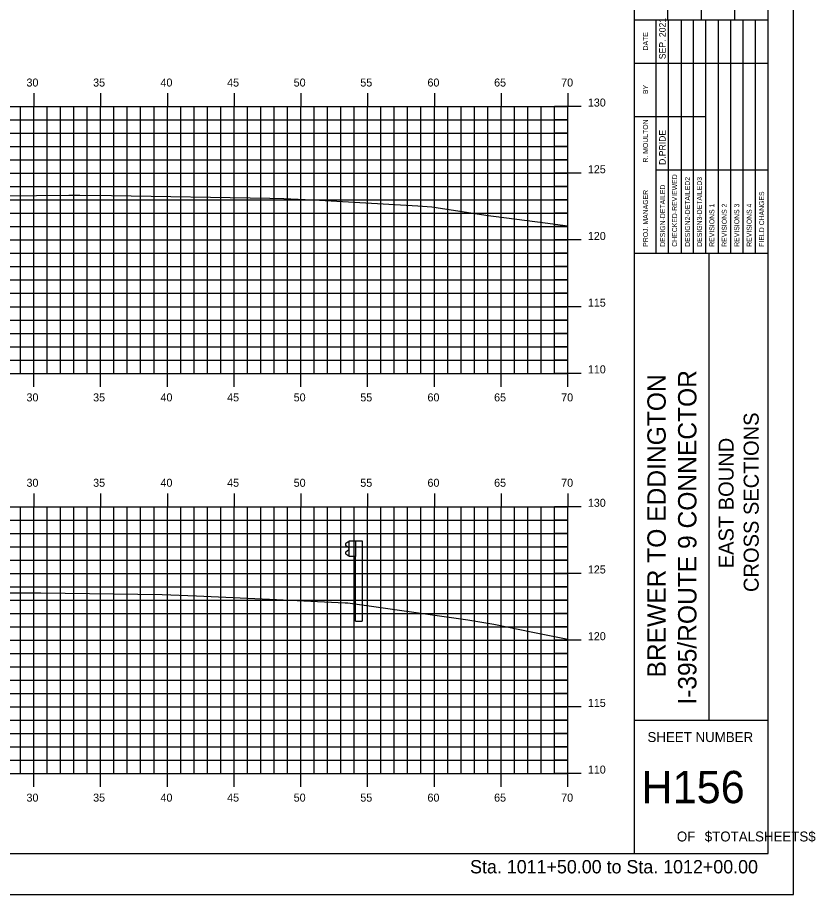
# Model space of a CAD drawing. Extents: x 852404 to 852575, y 365624 to 365734.
# Drawn here: x 852515.6 to 852575.3, y 365624 to 365689.7 of the extents above; entities that cross this region are included whole.
import ezdxf

# ---------------------------------------------------------------- set-up
doc = ezdxf.new("R2010")
doc.units = 0
for name, color, linetype in [('BORDER', 7, 'Continuous'), ('H_V ANNOTATION', 7, 'Continuous'), ('M_Guardrail', 7, 'Continuous'), ('M_Roadway_Centerline', 7, 'Continuous'), ('MAJOR', 7, 'Continuous'), ('MINOR', 7, 'Continuous'), ('PLOT BOUNDARY', 7, 'Continuous'), ('S_Roadway_Centerline', 7, 'Continuous')]:
    doc.layers.add(name, color=color, linetype=linetype)

msp = doc.modelspace()

# ---------------------------------------------------------------- linework, layer by layer
at = {"layer": 'BORDER'}
for p, q in [((852561.792, 365627.027), (852561.792, 365732.027)), ((852564.292, 365689.53), (852564.292, 365698.177)), ((852566.792, 365689.53), (852566.792, 365698.177)), ((852569.292, 365689.53), (852569.292, 365698.177)), ((852561.792, 365689.53), (852571.792, 365689.53)), ((852561.792, 365672.03), (852571.792, 365672.03)), ((852567.383, 365637.03), (852567.383, 365672.03)), ((852561.792, 365637.03), (852571.792, 365637.03))]:
    msp.add_line(p, q, dxfattribs=at)
msp.add_lwpolyline([(852411.792, 365627.027), (852571.792, 365627.027), (852571.792, 365732.027), (852411.792, 365732.027)], close=True, dxfattribs=at)
for points in [[(852563.407, 365686.28), (852563.407, 365689.53)], [(852564.339, 365672.033), (852564.339, 365689.53)], [(852565.271, 365689.53), (852565.271, 365672.033)], [(852566.203, 365672.033), (852566.203, 365689.53)], [(852567.135, 365672.033), (852567.135, 365689.53)], [(852568.066, 365672.033), (852568.066, 365689.53)], [(852568.998, 365672.033), (852568.998, 365689.53)], [(852569.93, 365672.033), (852569.93, 365689.53)], [(852570.861, 365672.033), (852570.861, 365689.53)], [(852563.408, 365672.033), (852563.408, 365688.824)], [(852561.792, 365686.28), (852571.792, 365686.28)], [(852561.792, 365682.28), (852563.408, 365682.28)], [(852563.407, 365682.28), (852567.134, 365682.28)], [(852563.407, 365678.28), (852571.792, 365678.28)]]:
    msp.add_lwpolyline(points, dxfattribs=at)
at = {"layer": 'M_Guardrail'}
for p, q in [((852540.407, 365650.464), (852540.896, 365650.464)), ((852540.407, 365649.297), (852540.407, 365650.464)), ((852540.896, 365650.464), (852541.388, 365650.464)), ((852540.896, 365650.464), (852540.896, 365649.297)), ((852541.388, 365650.464), (852541.388, 365644.464)), ((852540.308, 365650.369), (852540.165, 365650.269)), ((852540.165, 365650.126), (852540.36, 365649.99)), ((852540.36, 365649.77), (852540.165, 365649.634)), ((852540.407, 365650.391), (852540.325, 365650.376)), ((852540.394, 365649.926), (852540.394, 365649.835)), ((852540.165, 365649.491), (852540.308, 365649.391)), ((852540.325, 365649.384), (852540.407, 365649.37)), ((852540.896, 365649.297), (852540.407, 365649.297)), ((852540.896, 365644.464), (852540.896, 365649.297)), ((852540.896, 365644.464), (852541.388, 365644.464))]:
    msp.add_line(p, q, dxfattribs=at)
for centre, major_axis, start_param, end_param in [((852540.215, 365650.198), (-0.0877, 0), 5.323254, 7.243116), ((852540.332, 365650.335), (-0.0417, 0), 4.886922, 5.323254), ((852540.315, 365649.926), (0.0789, 0), 0, 0.959931), ((852540.315, 365649.835), (0.0789, 0), 5.323254, 6.283185), ((852540.215, 365649.563), (-0.0877, 0), 5.323254, 7.243116), ((852540.332, 365649.425), (-0.0417, 0), 0.959931, 1.396263)]:
    msp.add_ellipse(centre, major_axis=major_axis, ratio=0.995501, start_param=start_param, end_param=end_param, dxfattribs=at)
at = {"layer": 'MAJOR'}
for p, q in [((852516.792, 365684.029), (852516.792, 365683.027)), ((852521.792, 365684.029), (852521.792, 365683.027)), ((852526.792, 365684.029), (852526.792, 365683.027)), ((852531.792, 365684.029), (852531.792, 365683.027)), ((852536.792, 365684.029), (852536.792, 365683.027)), ((852541.792, 365684.029), (852541.792, 365683.027)), ((852546.792, 365684.029), (852546.792, 365683.027)), ((852551.792, 365684.029), (852551.792, 365683.027)), ((852556.792, 365684.029), (852556.792, 365683.027)), ((852416.792, 365683.027), (852556.792, 365683.027)), ((852416.792, 365683.027), (852556.792, 365683.027)), ((852516.792, 365663.027), (852516.792, 365683.027)), ((852521.792, 365663.027), (852521.792, 365683.027)), ((852526.792, 365663.027), (852526.792, 365683.027)), ((852531.792, 365663.027), (852531.792, 365683.027)), ((852536.792, 365663.027), (852536.792, 365683.027)), ((852541.792, 365663.027), (852541.792, 365683.027)), ((852546.792, 365663.027), (852546.792, 365683.027)), ((852551.792, 365663.027), (852551.792, 365683.027)), ((852557.794, 365683.027), (852555.79, 365683.027)), ((852556.792, 365663.027), (852556.792, 365683.027)), ((852556.792, 365663.027), (852556.792, 365683.027)), ((852416.792, 365678.027), (852556.792, 365678.027)), ((852557.794, 365678.027), (852555.79, 365678.027)), ((852416.792, 365673.027), (852556.792, 365673.027)), ((852557.794, 365673.027), (852555.79, 365673.027)), ((852416.792, 365668.027), (852556.792, 365668.027)), ((852557.794, 365668.027), (852555.79, 365668.027)), ((852416.792, 365663.027), (852556.792, 365663.027)), ((852416.792, 365663.027), (852556.792, 365663.027)), ((852516.792, 365662.025), (852516.792, 365663.027)), ((852521.792, 365662.025), (852521.792, 365663.027)), ((852526.792, 365662.025), (852526.792, 365663.027)), ((852531.792, 365662.025), (852531.792, 365663.027)), ((852536.792, 365662.025), (852536.792, 365663.027)), ((852541.792, 365662.025), (852541.792, 365663.027)), ((852546.792, 365662.025), (852546.792, 365663.027)), ((852551.792, 365662.025), (852551.792, 365663.027)), ((852557.794, 365663.027), (852555.79, 365663.027)), ((852556.792, 365662.025), (852556.792, 365663.027)), ((852516.792, 365654.029), (852516.792, 365653.027)), ((852521.792, 365654.029), (852521.792, 365653.027)), ((852526.792, 365654.029), (852526.792, 365653.027)), ((852531.792, 365654.029), (852531.792, 365653.027)), ((852536.792, 365654.029), (852536.792, 365653.027)), ((852541.792, 365654.029), (852541.792, 365653.027)), ((852546.792, 365654.029), (852546.792, 365653.027)), ((852551.792, 365654.029), (852551.792, 365653.027)), ((852556.792, 365654.029), (852556.792, 365653.027)), ((852416.792, 365653.027), (852556.792, 365653.027)), ((852416.792, 365653.027), (852556.792, 365653.027)), ((852516.792, 365633.027), (852516.792, 365653.027)), ((852521.792, 365633.027), (852521.792, 365653.027)), ((852526.792, 365633.027), (852526.792, 365653.027)), ((852531.792, 365633.027), (852531.792, 365653.027)), ((852536.792, 365633.027), (852536.792, 365653.027)), ((852541.792, 365633.027), (852541.792, 365653.027)), ((852546.792, 365633.027), (852546.792, 365653.027)), ((852551.792, 365633.027), (852551.792, 365653.027)), ((852557.794, 365653.027), (852555.79, 365653.027)), ((852556.792, 365633.027), (852556.792, 365653.027)), ((852556.792, 365633.027), (852556.792, 365653.027)), ((852416.792, 365648.027), (852556.792, 365648.027)), ((852557.794, 365648.027), (852555.79, 365648.027)), ((852416.792, 365643.027), (852556.792, 365643.027)), ((852557.794, 365643.027), (852555.79, 365643.027)), ((852416.792, 365638.027), (852556.792, 365638.027)), ((852557.794, 365638.027), (852555.79, 365638.027)), ((852416.792, 365633.027), (852556.792, 365633.027)), ((852416.792, 365633.027), (852556.792, 365633.027)), ((852516.792, 365632.025), (852516.792, 365633.027)), ((852521.792, 365632.025), (852521.792, 365633.027)), ((852526.792, 365632.025), (852526.792, 365633.027)), ((852531.792, 365632.025), (852531.792, 365633.027)), ((852536.792, 365632.025), (852536.792, 365633.027)), ((852541.792, 365632.025), (852541.792, 365633.027)), ((852546.792, 365632.025), (852546.792, 365633.027)), ((852551.792, 365632.025), (852551.792, 365633.027)), ((852557.794, 365633.027), (852555.79, 365633.027)), ((852556.792, 365632.025), (852556.792, 365633.027))]:
    msp.add_line(p, q, dxfattribs=at)
at = {"layer": 'MINOR'}
for p, q in [((852515.792, 365663.027), (852515.792, 365683.027)), ((852517.792, 365663.027), (852517.792, 365683.027)), ((852518.792, 365663.027), (852518.792, 365683.027)), ((852519.792, 365663.027), (852519.792, 365683.027)), ((852520.792, 365663.027), (852520.792, 365683.027)), ((852522.792, 365663.027), (852522.792, 365683.027)), ((852523.792, 365663.027), (852523.792, 365683.027)), ((852524.792, 365663.027), (852524.792, 365683.027)), ((852525.792, 365663.027), (852525.792, 365683.027)), ((852527.792, 365663.027), (852527.792, 365683.027)), ((852528.792, 365663.027), (852528.792, 365683.027)), ((852529.792, 365663.027), (852529.792, 365683.027)), ((852530.792, 365663.027), (852530.792, 365683.027)), ((852532.792, 365663.027), (852532.792, 365683.027)), ((852533.792, 365663.027), (852533.792, 365683.027)), ((852534.792, 365663.027), (852534.792, 365683.027)), ((852535.792, 365663.027), (852535.792, 365683.027)), ((852537.792, 365663.027), (852537.792, 365683.027)), ((852538.792, 365663.027), (852538.792, 365683.027)), ((852539.792, 365663.027), (852539.792, 365683.027)), ((852540.792, 365663.027), (852540.792, 365683.027)), ((852542.792, 365663.027), (852542.792, 365683.027)), ((852543.792, 365663.027), (852543.792, 365683.027)), ((852544.792, 365663.027), (852544.792, 365683.027)), ((852545.792, 365663.027), (852545.792, 365683.027)), ((852547.792, 365663.027), (852547.792, 365683.027)), ((852548.792, 365663.027), (852548.792, 365683.027)), ((852549.792, 365663.027), (852549.792, 365683.027)), ((852550.792, 365663.027), (852550.792, 365683.027)), ((852552.792, 365663.027), (852552.792, 365683.027)), ((852553.792, 365663.027), (852553.792, 365683.027)), ((852554.792, 365663.027), (852554.792, 365683.027)), ((852555.792, 365663.027), (852555.792, 365683.027)), ((852416.792, 365682.027), (852556.792, 365682.027)), ((852556.792, 365682.027), (852555.79, 365682.027)), ((852416.792, 365681.027), (852556.792, 365681.027)), ((852556.792, 365681.027), (852555.79, 365681.027)), ((852416.792, 365680.027), (852556.792, 365680.027)), ((852556.792, 365680.027), (852555.79, 365680.027)), ((852416.792, 365679.027), (852556.792, 365679.027)), ((852556.792, 365679.027), (852555.79, 365679.027)), ((852416.792, 365677.027), (852556.792, 365677.027)), ((852556.792, 365677.027), (852555.79, 365677.027)), ((852416.792, 365676.027), (852556.792, 365676.027)), ((852556.792, 365676.027), (852555.79, 365676.027)), ((852416.792, 365675.027), (852556.792, 365675.027)), ((852556.792, 365675.027), (852555.79, 365675.027)), ((852416.792, 365674.027), (852556.792, 365674.027)), ((852556.792, 365674.027), (852555.79, 365674.027)), ((852416.792, 365672.027), (852556.792, 365672.027)), ((852556.792, 365672.027), (852555.79, 365672.027)), ((852416.792, 365671.027), (852556.792, 365671.027)), ((852556.792, 365671.027), (852555.79, 365671.027)), ((852416.792, 365670.027), (852556.792, 365670.027)), ((852556.792, 365670.027), (852555.79, 365670.027)), ((852416.792, 365669.027), (852556.792, 365669.027)), ((852556.792, 365669.027), (852555.79, 365669.027)), ((852416.792, 365667.027), (852556.792, 365667.027)), ((852556.792, 365667.027), (852555.79, 365667.027)), ((852416.792, 365666.027), (852556.792, 365666.027)), ((852556.792, 365666.027), (852555.79, 365666.027)), ((852416.792, 365665.027), (852556.792, 365665.027)), ((852556.792, 365665.027), (852555.79, 365665.027)), ((852416.792, 365664.027), (852556.792, 365664.027)), ((852556.792, 365664.027), (852555.79, 365664.027)), ((852515.792, 365633.027), (852515.792, 365653.027)), ((852517.792, 365633.027), (852517.792, 365653.027)), ((852518.792, 365633.027), (852518.792, 365653.027)), ((852519.792, 365633.027), (852519.792, 365653.027)), ((852520.792, 365633.027), (852520.792, 365653.027)), ((852522.792, 365633.027), (852522.792, 365653.027)), ((852523.792, 365633.027), (852523.792, 365653.027)), ((852524.792, 365633.027), (852524.792, 365653.027)), ((852525.792, 365633.027), (852525.792, 365653.027)), ((852527.792, 365633.027), (852527.792, 365653.027)), ((852528.792, 365633.027), (852528.792, 365653.027)), ((852529.792, 365633.027), (852529.792, 365653.027)), ((852530.792, 365633.027), (852530.792, 365653.027)), ((852532.792, 365633.027), (852532.792, 365653.027)), ((852533.792, 365633.027), (852533.792, 365653.027)), ((852534.792, 365633.027), (852534.792, 365653.027)), ((852535.792, 365633.027), (852535.792, 365653.027)), ((852537.792, 365633.027), (852537.792, 365653.027)), ((852538.792, 365633.027), (852538.792, 365653.027)), ((852539.792, 365633.027), (852539.792, 365653.027)), ((852540.792, 365633.027), (852540.792, 365653.027)), ((852542.792, 365633.027), (852542.792, 365653.027)), ((852543.792, 365633.027), (852543.792, 365653.027)), ((852544.792, 365633.027), (852544.792, 365653.027)), ((852545.792, 365633.027), (852545.792, 365653.027)), ((852547.792, 365633.027), (852547.792, 365653.027)), ((852548.792, 365633.027), (852548.792, 365653.027)), ((852549.792, 365633.027), (852549.792, 365653.027)), ((852550.792, 365633.027), (852550.792, 365653.027)), ((852552.792, 365633.027), (852552.792, 365653.027)), ((852553.792, 365633.027), (852553.792, 365653.027)), ((852554.792, 365633.027), (852554.792, 365653.027)), ((852555.792, 365633.027), (852555.792, 365653.027)), ((852416.792, 365652.027), (852556.792, 365652.027)), ((852556.792, 365652.027), (852555.79, 365652.027)), ((852416.792, 365651.027), (852556.792, 365651.027)), ((852556.792, 365651.027), (852555.79, 365651.027)), ((852416.792, 365650.027), (852556.792, 365650.027)), ((852556.792, 365650.027), (852555.79, 365650.027)), ((852416.792, 365649.027), (852556.792, 365649.027)), ((852556.792, 365649.027), (852555.79, 365649.027)), ((852416.792, 365647.027), (852556.792, 365647.027)), ((852556.792, 365647.027), (852555.79, 365647.027)), ((852416.792, 365646.027), (852556.792, 365646.027)), ((852556.792, 365646.027), (852555.79, 365646.027)), ((852416.792, 365645.027), (852556.792, 365645.027)), ((852556.792, 365645.027), (852555.79, 365645.027)), ((852416.792, 365644.027), (852556.792, 365644.027)), ((852556.792, 365644.027), (852555.79, 365644.027)), ((852416.792, 365642.027), (852556.792, 365642.027)), ((852556.792, 365642.027), (852555.79, 365642.027)), ((852416.792, 365641.027), (852556.792, 365641.027)), ((852556.792, 365641.027), (852555.79, 365641.027)), ((852416.792, 365640.027), (852556.792, 365640.027)), ((852556.792, 365640.027), (852555.79, 365640.027)), ((852416.792, 365639.027), (852556.792, 365639.027)), ((852556.792, 365639.027), (852555.79, 365639.027)), ((852416.792, 365637.027), (852556.792, 365637.027)), ((852556.792, 365637.027), (852555.79, 365637.027)), ((852416.792, 365636.027), (852556.792, 365636.027)), ((852556.792, 365636.027), (852555.79, 365636.027)), ((852416.792, 365635.027), (852556.792, 365635.027)), ((852556.792, 365635.027), (852555.79, 365635.027)), ((852416.792, 365634.027), (852556.792, 365634.027)), ((852556.792, 365634.027), (852555.79, 365634.027))]:
    msp.add_line(p, q, dxfattribs=at)
at = {"layer": 'PLOT BOUNDARY'}
msp.add_lwpolyline([(852403.699, 365623.968), (852573.699, 365623.968), (852573.699, 365733.968), (852403.699, 365733.968)], close=True, dxfattribs=at)
at = {"layer": 'S_Roadway_Centerline'}
for points in [[(852512.087, 365676.312), (852519.423, 365676.382), (852520.245, 365676.382), (852522.605, 365676.362), (852534.472, 365676.154), (852535.51, 365676.139), (852538.19, 365676.015), (852545.547, 365675.583), (852546.61, 365675.503), (852550.653, 365674.892), (852555.096, 365674.316), (852556.792, 365674.074)], [(852514.953, 365646.571), (852516.292, 365646.575), (852517.315, 365646.569), (852526.407, 365646.462), (852528.971, 365646.362), (852534.446, 365646.095), (852540.113, 365645.836), (852540.315, 365645.823), (852549.292, 365644.561), (852551.256, 365644.218), (852554.042, 365643.664), (852556.792, 365643.116)]]:
    msp.add_lwpolyline(points, dxfattribs=at)

# ---------------------------------------------------------------- texts
at = {"layer": 'BORDER'}
for s, height, p in [('SEP. 2021', 0.4845, (852564.115, 365686.575)), ('DATE', 0.3714, (852562.796, 365687.235)), ('BY', 0.3714, (852562.796, 365683.965)), ('R. MOULTON', 0.3727, (852562.796, 365678.832)), ('D.PRIDE', 0.4845, (852564.115, 365678.653)), ('CHECKED-REVIEWED', 0.37275, (852564.973, 365672.518)), ('DESIGN2-DETAILED2', 0.37275, (852565.942, 365672.518)), ('DESIGN3-DETAILED3', 0.37275, (852566.836, 365672.518)), ('DESIGN-DETAILED', 0.37275, (852564.079, 365672.518)), ('PROJ. MANAGER', 0.37275, (852562.796, 365672.518)), ('FIELD CHANGES', 0.37275, (852571.495, 365672.518)), ('REVISIONS 1', 0.37275, (852567.768, 365672.518)), ('REVISIONS 2', 0.37275, (852568.7, 365672.518)), ('REVISIONS 3', 0.37275, (852569.631, 365672.518)), ('REVISIONS 4', 0.37275, (852570.563, 365672.518)), ('I-395/ROUTE 9 CONNECTOR', 1.37787, (852566.427, 365638.192)), ('BREWER TO EDDINGTON', 1.37787, (852564.126, 365640.231)), ('CROSS SECTIONS', 1.125, (852571.089, 365646.638)), ('EAST BOUND', 1.125, (852569.21, 365648.418))]:
    msp.add_text(s, height=height, rotation=90, dxfattribs=at).set_placement(p)
for s, height, p in [('SHEET NUMBER', 0.74527, (852562.757, 365635.393)), ('H156', 2.4194, (852562.307, 365630.809)), ('$TOTALSHEETS$', 0.74527, (852567.049, 365627.94)), ('OF', 0.7453, (852564.959, 365627.94))]:
    msp.add_text(s, height=height, dxfattribs=at).set_placement(p)
at = {"layer": 'H_V ANNOTATION'}
for s, height, p in [('30', 0.6, (852516.241, 365684.527)), ('35', 0.6, (852521.233, 365684.527)), ('40', 0.6, (852526.278, 365684.527)), ('45', 0.6, (852531.27, 365684.527)), ('50', 0.6, (852536.256, 365684.527)), ('55', 0.6, (852541.248, 365684.527)), ('60', 0.6, (852546.278, 365684.527)), ('65', 0.6, (852551.27, 365684.527)), ('70', 0.6, (852556.294, 365684.527)), ('130', 0.6, (852558.292, 365683.027)), ('125', 0.6, (852558.292, 365678.027)), ('120', 0.6, (852558.292, 365673.027)), ('115', 0.6, (852558.292, 365668.027)), ('110', 0.6, (852558.292, 365663.027)), ('30', 0.6, (852516.241, 365660.927)), ('35', 0.6, (852521.233, 365660.927)), ('40', 0.6, (852526.278, 365660.927)), ('45', 0.6, (852531.27, 365660.927)), ('50', 0.6, (852536.256, 365660.927)), ('55', 0.6, (852541.248, 365660.927)), ('60', 0.6, (852546.278, 365660.927)), ('65', 0.6, (852551.27, 365660.927)), ('70', 0.6, (852556.294, 365660.927)), ('30', 0.6, (852516.241, 365654.527)), ('35', 0.6, (852521.233, 365654.527)), ('40', 0.6, (852526.278, 365654.527)), ('45', 0.6, (852531.27, 365654.527)), ('50', 0.6, (852536.256, 365654.527)), ('55', 0.6, (852541.248, 365654.527)), ('60', 0.6, (852546.278, 365654.527)), ('65', 0.6, (852551.27, 365654.527)), ('70', 0.6, (852556.294, 365654.527)), ('130', 0.6, (852558.292, 365653.027)), ('125', 0.6, (852558.292, 365648.027)), ('120', 0.6, (852558.292, 365643.027)), ('115', 0.6, (852558.292, 365638.027)), ('110', 0.6, (852558.292, 365633.027)), ('30', 0.6, (852516.241, 365630.927)), ('35', 0.6, (852521.233, 365630.927)), ('40', 0.6, (852526.278, 365630.927)), ('45', 0.6, (852531.27, 365630.927)), ('50', 0.6, (852536.256, 365630.927)), ('55', 0.6, (852541.248, 365630.927)), ('60', 0.6, (852546.278, 365630.927)), ('65', 0.6, (852551.27, 365630.927)), ('70', 0.6, (852556.294, 365630.927)), ('Sta. 1011+50.00 to Sta. 1012+00.00', 1.0002, (852549.468, 365625.547))]:
    msp.add_text(s, height=height, dxfattribs=at).set_placement(p)
at = {"layer": 'M_Roadway_Centerline'}
for s, p in [('C', (852516.287, 365646.575)), ('L', (852516.292, 365646.567))]:
    msp.add_text(s, height=0.0146, dxfattribs=at).set_placement(p)

doc.saveas('drawing.dxf')
